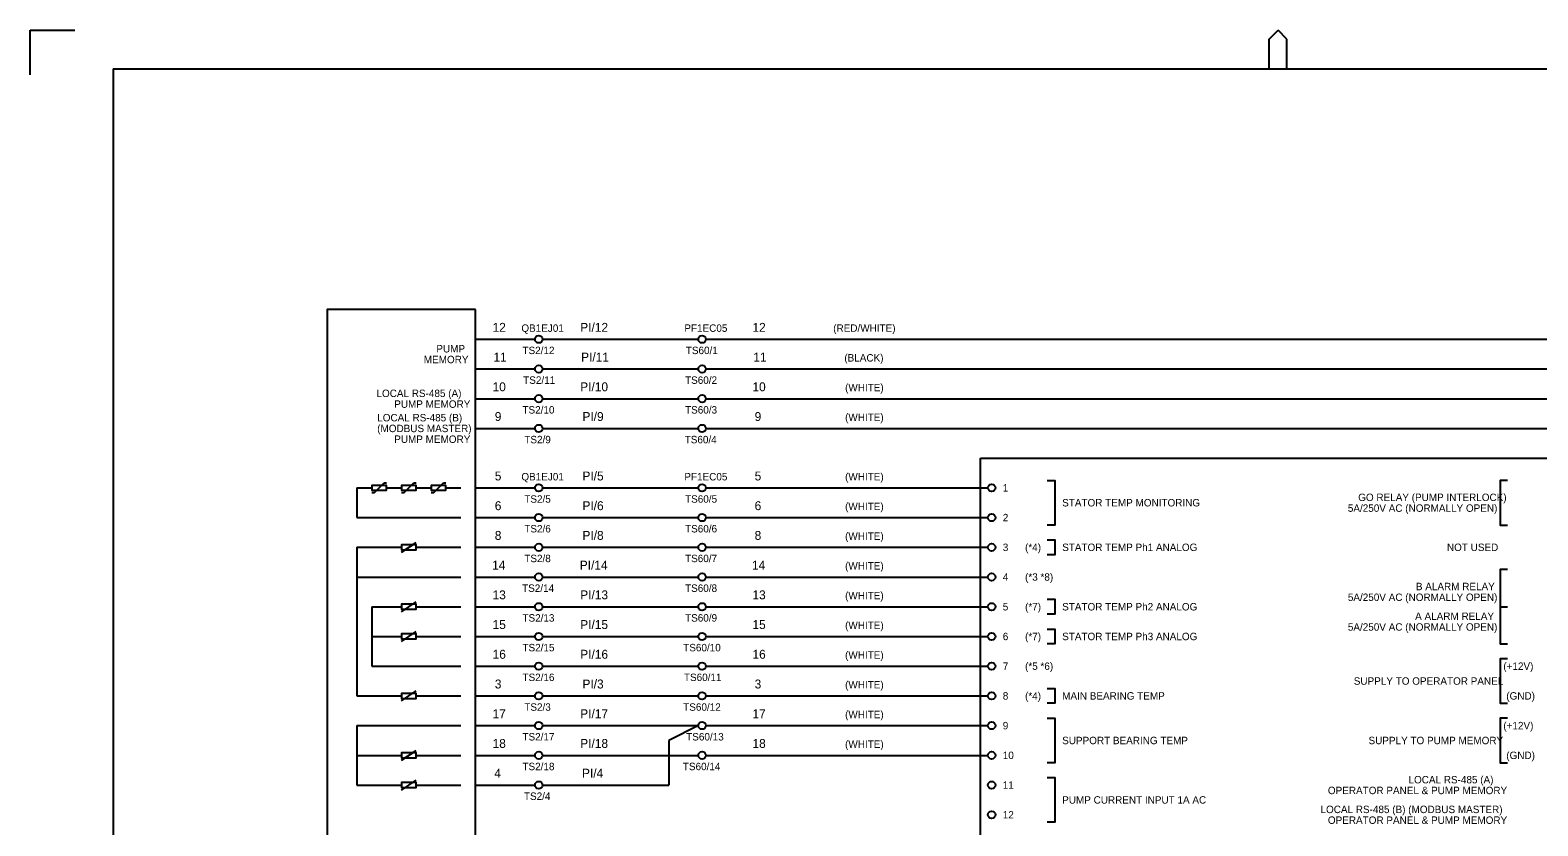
# Model space of a CAD drawing. Extents: x 0 to 841, y 0 to 594.
# Drawn here: x 0 to 508, y 326 to 594 of the extents above; entities that cross this region are included whole.
import ezdxf

# ---------------------------------------------------------------- set-up
doc = ezdxf.new("R2010")
doc.units = 0
for name, color, linetype in [('A1BORDER', 7, 'Continuous'), ('Level 1', 7, 'Continuous'), ('Level 10', 7, 'Continuous'), ('Level 5', 7, 'Continuous'), ('Level 6', 7, 'Continuous')]:
    doc.layers.add(name, color=color, linetype=linetype)

msp = doc.modelspace()

# ---------------------------------------------------------------- linework, layer by layer
at = {"layer": 'A1BORDER'}
for p, q in [((0, 594), (15, 594)), ((0, 579), (0, 594)), ((417.19, 591), (420.19, 594)), ((423.19, 591), (420.19, 594)), ((417.19, 581), (417.19, 591)), ((423.19, 581), (423.19, 591)), ((28, 581), (829, 581)), ((28, 581), (28, 15))]:
    msp.add_line(p, q, dxfattribs=at)
at = {"layer": 'Level 1'}
for p, q in [((227.5, 490), (590, 490)), ((227.5, 480), (580, 480)), ((227.5, 470), (620, 470)), ((227.5, 460), (610, 460)), ((110, 440), (115, 440)), ((110, 440), (110, 430)), ((115.83, 438.33), (115, 438.33)), ((115.83, 438.33), (119.17, 441.67)), ((119.17, 441.67), (120, 441.67)), ((120, 440), (125, 440)), ((125.83, 438.33), (125, 438.33)), ((125.83, 438.33), (129.17, 441.67)), ((129.17, 441.67), (130, 441.67)), ((130, 440), (135, 440)), ((135.83, 438.33), (135, 438.33)), ((135.83, 438.33), (139.17, 441.67)), ((139.17, 441.67), (140, 441.67)), ((140, 440), (145, 440)), ((227.5, 440), (322.5, 440)), ((110, 430), (145, 430)), ((227.5, 430), (322.5, 430)), ((125, 418.33), (130, 421.67)), ((110, 420), (125, 420)), ((110, 420), (110, 370)), ((130, 420), (145, 420)), ((227.5, 420), (322.5, 420)), ((110, 410), (145, 410)), ((227.5, 410), (322.5, 410)), ((125, 398.33), (130, 401.67)), ((115, 400), (125, 400)), ((115, 400), (115, 380)), ((130, 400), (145, 400)), ((227.5, 400), (322.5, 400)), ((495, 400), (497.5, 400)), ((125, 388.33), (130, 391.67)), ((115, 390), (125, 390)), ((130, 390), (145, 390)), ((227.5, 390), (322.5, 390)), ((115, 380), (145, 380)), ((227.5, 380), (322.5, 380)), ((125, 368.33), (130, 371.67)), ((110, 370), (125, 370)), ((130, 370), (145, 370)), ((227.5, 370), (322.5, 370)), ((110, 360), (110, 340)), ((110, 360), (145, 360)), ((225, 360), (215, 355)), ((227.5, 360), (322.5, 360)), ((125, 348.33), (130, 351.67)), ((215, 355), (215, 340)), ((215, 355), (215, 340)), ((110, 350), (125, 350)), ((130, 350), (145, 350)), ((227.5, 350), (322.5, 350)), ((125, 338.33), (130, 341.67)), ((110, 340), (125, 340)), ((130, 340), (145, 340))]:
    msp.add_line(p, q, dxfattribs=at)
for points in [[(150, 500), (100, 500), (100, 220), (150, 220)], [(320, 450), (520, 450), (520, 180), (320, 180)]]:
    msp.add_lwpolyline(points, close=True, dxfattribs=at)
for points in [[(342.5, 442.5), (345, 442.5), (345, 427.5), (342.5, 427.5)], [(497.5, 442.5), (495, 442.5), (495, 427.5), (497.5, 427.5)], [(342.5, 422.5), (345, 422.5), (345, 417.5), (342.5, 417.5)], [(497.5, 412.5), (495, 412.5), (495, 387.5), (497.5, 387.5)], [(342.5, 402.5), (345, 402.5), (345, 397.5), (342.5, 397.5)], [(342.5, 392.5), (345, 392.5), (345, 387.5), (342.5, 387.5)], [(497.5, 382.5), (495, 382.5), (495, 367.5), (497.5, 367.5)], [(342.5, 372.5), (345, 372.5), (345, 367.5), (342.5, 367.5)], [(342.5, 362.5), (345, 362.5), (345, 347.5), (342.5, 347.5)], [(497.5, 362.5), (495, 362.5), (495, 347.5), (497.5, 347.5)], [(342.5, 342.5), (345, 342.5), (345, 327.5), (342.5, 327.5)]]:
    msp.add_lwpolyline(points, dxfattribs=at)
at = {"layer": 'Level 10'}
for points in [[(115, 440), (115, 439.17), (120, 439.17), (120, 440.83), (115, 440.83), (115, 440)], [(125, 440), (125, 439.17), (130, 439.17), (130, 440.83), (125, 440.83), (125, 440)], [(135, 440), (135, 439.17), (140, 439.17), (140, 440.83), (135, 440.83), (135, 440)], [(125, 420), (125, 419.17), (130, 419.17), (130, 420.83), (125, 420.83), (125, 420)], [(125, 400), (125, 399.17), (130, 399.17), (130, 400.83), (125, 400.83), (125, 400)], [(125, 390), (125, 389.17), (130, 389.17), (130, 390.83), (125, 390.83), (125, 390)], [(125, 370), (125, 369.17), (130, 369.17), (130, 370.83), (125, 370.83), (125, 370)], [(125, 350), (125, 349.17), (130, 349.17), (130, 350.83), (125, 350.83), (125, 350)], [(125, 340), (125, 339.17), (130, 339.17), (130, 340.83), (125, 340.83), (125, 340)]]:
    msp.add_lwpolyline(points, dxfattribs=at)
at = {"layer": 'Level 5'}
for centre in [(171.25, 490), (226.25, 490), (171.25, 480), (226.25, 480), (171.25, 470), (226.25, 470), (171.25, 460), (226.25, 460), (171.25, 440), (226.25, 440), (323.75, 440), (171.25, 430), (226.25, 430), (323.75, 430), (171.25, 420), (226.25, 420), (323.75, 420), (171.25, 410), (226.25, 410), (323.75, 410), (171.25, 400), (226.25, 400), (323.75, 400), (171.25, 390), (226.25, 390), (323.75, 390), (171.25, 380), (226.25, 380), (323.75, 380), (171.25, 370), (226.25, 370), (323.75, 370), (171.25, 360), (226.25, 360), (323.75, 360), (171.25, 350), (226.25, 350), (323.75, 350), (171.25, 340), (323.75, 340), (323.75, 330)]:
    msp.add_circle(centre, 1.25, dxfattribs=at)
at = {"layer": 'Level 6'}
for p, q in [((150, 490), (170, 490)), ((172.5, 490), (225, 490)), ((150, 480), (170, 480)), ((172.5, 480), (225, 480)), ((150, 470), (170, 470)), ((172.5, 470), (225, 470)), ((150, 460), (170, 460)), ((172.5, 460), (225, 460)), ((150, 440), (170, 440)), ((172.5, 440), (225, 440)), ((150, 430), (170, 430)), ((172.5, 430), (225, 430)), ((150, 420), (170, 420)), ((172.5, 420), (225, 420)), ((150, 410), (170, 410)), ((172.5, 410), (225, 410)), ((150, 400), (170, 400)), ((172.5, 400), (225, 400)), ((150, 390), (170, 390)), ((172.5, 390), (225, 390)), ((150, 380), (170, 380)), ((172.5, 380), (225, 380)), ((150, 370), (170, 370)), ((172.5, 370), (225, 370)), ((150, 360), (170, 360)), ((172.5, 360), (225, 360)), ((150, 350), (170, 350)), ((172.5, 350), (225, 350)), ((150, 340), (170, 340)), ((172.5, 340), (215, 340))]:
    msp.add_line(p, q, dxfattribs=at)

# ---------------------------------------------------------------- texts
at = {"layer": 'Level 1'}
for s, p in [('QB1EJ01', (165.4, 492.5)), ('PF1EC05', (220.28, 492.5)), ('PUMP', (136.78, 485.56)), ('TS2/12', (165.77, 485)), ('TS60/1', (220.77, 485)), ('MEMORY', (132.55, 481.94)), ('TS2/11', (166.02, 475)), ('TS60/2', (220.52, 475)), ('LOCAL RS-485 (A)', (116.61, 470.56)), ('PUMP MEMORY', (122.59, 466.94)), ('TS2/10', (165.77, 465)), ('TS60/3', (220.52, 465)), ('LOCAL RS-485 (B)', (116.86, 462.37)), ('(MODBUS MASTER)', (116.86, 458.75)), ('PUMP MEMORY', (122.59, 455.13)), ('TS2/9', (166.39, 455)), ('TS60/4', (220.4, 455)), ('QB1EJ01', (165.4, 442.5)), ('PF1EC05', (220.28, 442.5)), ('TS2/5', (166.39, 435)), ('TS60/5', (220.52, 435)), ('1', (327.5, 438.75)), ('GO RELAY (PUMP INTERLOCK)', (447.18, 435.56)), ('STATOR TEMP MONITORING', (347.5, 433.75)), ('5A/250V AC (NORMALLY OPEN)', (443.69, 431.94)), ('TS2/6', (166.39, 425)), ('TS60/6', (220.52, 425)), ('2', (327.5, 428.75)), ('(*4)', (335, 418.75)), ('STATOR TEMP Ph1 ANALOG', (347.5, 418.75)), ('TS2/8', (166.39, 415)), ('TS60/7', (220.52, 415)), ('3', (327.5, 418.75)), ('NOT USED', (477.06, 418.75)), ('4', (327.5, 408.75)), ('(*3 *8)', (335, 408.75)), ('TS2/14', (165.65, 405)), ('TS60/8', (220.52, 405)), ('B ALARM RELAY', (466.6, 405.56)), ('5', (327.5, 398.75)), ('(*7)', (335, 398.75)), ('STATOR TEMP Ph2 ANALOG', (347.5, 398.75)), ('5A/250V AC (NORMALLY OPEN)', (443.69, 401.94)), ('TS2/13', (165.77, 395)), ('TS60/9', (220.52, 395)), ('A ALARM RELAY', (466.35, 395.56)), ('6', (327.5, 388.75)), ('(*7)', (335, 388.75)), ('STATOR TEMP Ph3 ANALOG', (347.5, 388.75)), ('5A/250V AC (NORMALLY OPEN)', (443.69, 391.94)), ('TS2/15', (165.77, 385)), ('TS60/10', (219.9, 385)), ('7', (327.5, 378.75)), ('(*5 *6)', (335, 378.75)), ('(+12V)', (496.04, 378.75)), ('TS2/16', (165.77, 375)), ('TS60/11', (220.15, 375)), ('SUPPLY TO OPERATOR PANEL', (445.68, 373.75)), ('8', (327.5, 368.75)), ('(*4)', (335, 368.75)), ('MAIN BEARING TEMP', (347.5, 368.75)), ('(GND)', (497.04, 368.75)), ('TS2/3', (166.39, 365)), ('TS60/12', (219.9, 365)), ('9', (327.5, 358.75)), ('(+12V)', (496.04, 358.75)), ('TS2/17', (165.77, 355)), ('TS60/13', (220.9, 355)), ('SUPPORT BEARING TEMP', (347.5, 353.75)), ('SUPPLY TO PUMP MEMORY', (450.66, 353.75)), ('10', (327.5, 348.75)), ('(GND)', (497.04, 348.75)), ('TS2/18', (165.77, 345)), ('TS60/14', (219.78, 345)), ('11', (327.5, 338.75)), ('LOCAL RS-485 (A)', (464.11, 340.56)), ('TS2/4', (166.27, 335)), ('PUMP CURRENT INPUT 1A AC', (347.5, 333.75)), ('OPERATOR PANEL & PUMP MEMORY', (436.97, 336.94)), ('12', (327.5, 328.75)), ('LOCAL RS-485 (B) (MODBUS MASTER)', (434.48, 330.56)), ('OPERATOR PANEL & PUMP MEMORY', (436.97, 326.94))]:
    msp.add_text(s, height=2.5, dxfattribs=at).set_placement(p)
at = {"layer": 'Level 5'}
for s, height, p in [('12', 3, (155.71, 492.5)), ('PI/12', 3, (185.22, 492.5)), ('12', 3, (243.21, 492.5)), ('(RED/WHITE)', 2.5, (270.41, 492.5)), ('11', 3, (156.01, 482.5)), ('PI/11', 3, (185.52, 482.5)), ('11', 3, (243.51, 482.5)), ('(BLACK)', 2.5, (274.15, 482.5)), ('10', 3, (155.71, 472.5)), ('PI/10', 3, (185.22, 472.5)), ('10', 3, (243.21, 472.5)), ('(WHITE)', 2.5, (274.4, 472.5)), ('9', 3, (156.45, 462.5)), ('PI/9', 3, (185.97, 462.5)), ('9', 3, (243.95, 462.5)), ('(WHITE)', 2.5, (274.4, 462.5)), ('5', 3, (156.45, 442.5)), ('PI/5', 3, (185.97, 442.5)), ('5', 3, (243.95, 442.5)), ('(WHITE)', 2.5, (274.4, 442.5)), ('6', 3, (156.45, 432.5)), ('PI/6', 3, (185.97, 432.5)), ('6', 3, (243.95, 432.5)), ('(WHITE)', 2.5, (274.4, 432.5)), ('8', 3, (156.45, 422.5)), ('PI/8', 3, (185.97, 422.5)), ('8', 3, (243.95, 422.5)), ('(WHITE)', 2.5, (274.4, 422.5)), ('14', 3, (155.56, 412.5)), ('PI/14', 3, (185.07, 412.5)), ('14', 3, (243.06, 412.5)), ('(WHITE)', 2.5, (274.4, 412.5)), ('13', 3, (155.71, 402.5)), ('PI/13', 3, (185.22, 402.5)), ('13', 3, (243.21, 402.5)), ('(WHITE)', 2.5, (274.4, 402.5)), ('15', 3, (155.71, 392.5)), ('PI/15', 3, (185.22, 392.5)), ('15', 3, (243.21, 392.5)), ('(WHITE)', 2.5, (274.4, 392.5)), ('16', 3, (155.71, 382.5)), ('PI/16', 3, (185.22, 382.5)), ('16', 3, (243.21, 382.5)), ('(WHITE)', 2.5, (274.4, 382.5)), ('3', 3, (156.45, 372.5)), ('PI/3', 3, (185.97, 372.5)), ('3', 3, (243.95, 372.5)), ('(WHITE)', 2.5, (274.4, 372.5)), ('PI/17', 3, (185.22, 362.5)), ('17', 3, (155.71, 362.5)), ('17', 3, (243.21, 362.5)), ('(WHITE)', 2.5, (274.4, 362.5)), ('18', 3, (155.71, 352.5)), ('PI/18', 3, (185.22, 352.5)), ('18', 3, (243.21, 352.5)), ('(WHITE)', 2.5, (274.4, 352.5)), ('4', 3, (156.3, 342.5)), ('PI/4', 3, (185.82, 342.5))]:
    msp.add_text(s, height=height, dxfattribs=at).set_placement(p)

doc.saveas('drawing.dxf')
